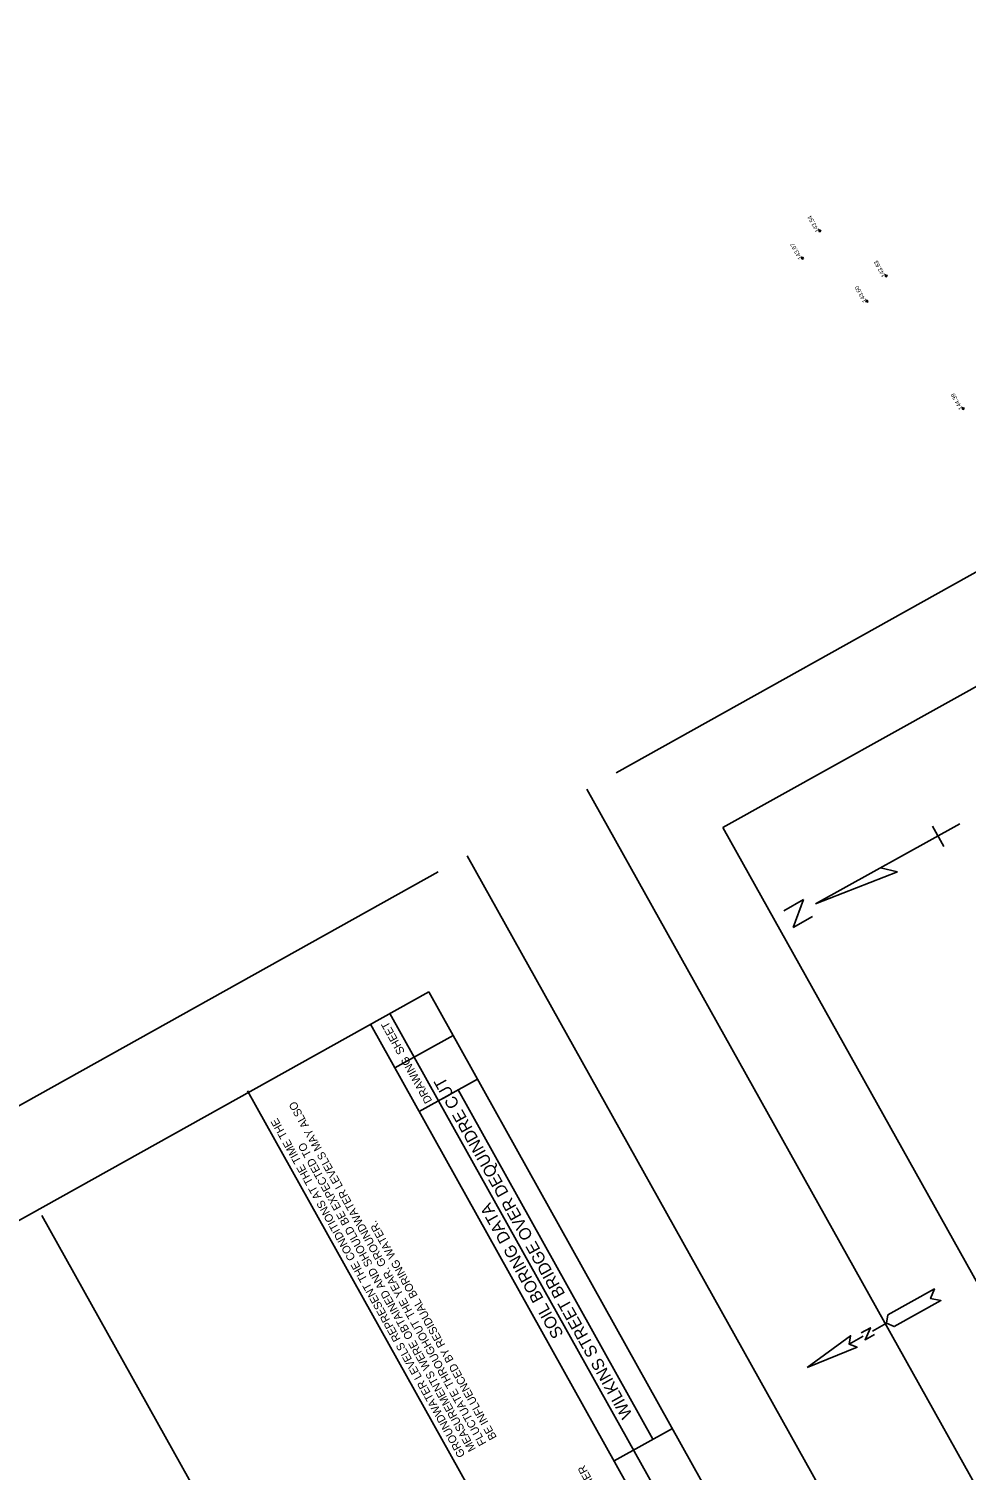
# Model space of a CAD drawing. Extents: x 13482447 to 13495412, y 324533 to 340229.
# Drawn here: x 13492579 to 13493141, y 331592 to 332457 of the extents above; entities that cross this region are included whole.
import ezdxf

# ---------------------------------------------------------------- set-up
doc = ezdxf.new("R2010")
doc.units = 0
for name, color, linetype in [('BORDER', 7, 'Continuous'), ('Default', 7, 'Continuous'), ('Level 1', 7, 'Continuous'), ('Level 63', 7, 'Continuous'), ('V-PVMT-IDEN', 7, 'Continuous'), ('V-TOPO-DRAN-SPOT', 7, 'Continuous')]:
    doc.layers.add(name, color=color, linetype=linetype)

# ---------------------------------------------------------------- blocks, each defined once
blk = doc.blocks.new('VERTN')
at = {"layer": 'Level 63'}
for p, q in [((0, 0.0104), (0, 0.0417)), ((0, -0.0417), (0, -0.0104))]:
    blk.add_line(p, q, dxfattribs=at)
for points in [[(0, 0.1354), (-0.013, 0.0312), (0, 0.0417), (0.013, 0.0312), (0, 0.1354)], [(-0.0078, -0.0104), (-0.0078, 0.0104), (0.0077, -0.0104), (0.0077, 0.0104)], [(0, -0.0417), (-0.013, -0.0521), (-0.013, -0.1562), (0, -0.1406), (0.013, -0.1562), (0.013, -0.0521), (0, -0.0417)]]:
    blk.add_lwpolyline(points, dxfattribs=at)

msp = doc.modelspace()

# ---------------------------------------------------------------- linework, layer by layer
at = {"layer": 'BORDER'}
for p, q in [((13493136.93, 331980.13), (13493050.27, 331932.13)), ((13493120.48, 331978.82), (13493127.24, 331966.62)), ((13493099.42, 331951.43), (13493089.37, 331953.79)), ((13493050.27, 331932.13), (13493099.42, 331951.43)), ((13493043.03, 331934.66), (13493031.26, 331928.03)), ((13493036.88, 331917.89), (13493043.03, 331934.66)), ((13493048.6, 331924.61), (13493036.88, 331917.89))]:
    msp.add_line(p, q, dxfattribs=at)
at = {"layer": 'Default'}
msp.add_lwpolyline([(13492586.34, 331745.09), (13492832.27, 331304.34)], dxfattribs=at)
at = {"layer": 'Level 1'}
for p, q in [((13493730.57, 332457.1), (13492930.67, 332010.77)), ((13493724.88, 332385.22), (13492994.84, 331977.87)), ((13493612.91, 330747.03), (13492913.2, 332001.03)), ((13493636.07, 330828.66), (13492994.84, 331977.87)), ((13493541.18, 330707.01), (13492841.48, 331961.01)), ((13492824.01, 331951.26), (13492024.11, 331504.93)), ((13492818.32, 331879.38), (13492088.28, 331472.03)), ((13493459.55, 330730.17), (13492818.32, 331879.38)), ((13493424.62, 330710.68), (13492783.39, 331859.89)), ((13492824.27, 331813.99), (13492795.03, 331866.38)), ((13492832.94, 331853.18), (13492798.01, 331833.69)), ((13492847.56, 331826.98), (13492812.62, 331807.49)), ((13493352.3, 330668.3), (13492709.75, 331819.87)), ((13492952.85, 331610.9), (13492835.91, 331820.49)), ((13493136.11, 331255.1), (13492824.27, 331813.99)), ((13492929.58, 331597.92), (13492964.52, 331617.41))]:
    msp.add_line(p, q, dxfattribs=at)
at = {"layer": 'V-TOPO-DRAN-SPOT'}
for p, q in [((13493052.07, 332335.47), (13493053.69, 332336.37)), ((13493053.35, 332335.08), (13493052.41, 332336.76)), ((13493041.66, 332319.07), (13493043.28, 332319.97)), ((13493042.93, 332318.68), (13493042, 332320.36)), ((13493091.84, 332308.5), (13493093.46, 332309.41)), ((13493093.11, 332308.12), (13493092.18, 332309.79)), ((13493080.33, 332293.3), (13493081.95, 332294.2)), ((13493081.61, 332292.91), (13493080.67, 332294.59)), ((13493138, 332228.89), (13493139.62, 332229.79)), ((13493139.28, 332228.5), (13493138.34, 332230.18))]:
    msp.add_line(p, q, dxfattribs=at)

# ---------------------------------------------------------------- block references
at = {"layer": 'V-PVMT-IDEN', "xscale": 307.2, "yscale": 307.2000000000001, "rotation": 119.16052892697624}
msp.add_blockref('VERTN', (13493081.66, 331674.23), dxfattribs=at)

# ---------------------------------------------------------------- texts
at = {"layer": 'BORDER'}
for s, p in [('FLUCTUATE THROUGHOUT THE YEAR. GROUNDWATER LEVELS MAY ALSO ', (13492853.03, 331608.61)), ('GROUNDWATER LEVELS REPRESENT THE CONDITIONS AT THE TIME THE ', (13492840.45, 331601.59)), ('MEASUREMENTS WERE OBTAINED AND SHOULD BE EXPECTED TO ', (13492846.74, 331605.1)), ('BE INFLUENCED BY RESIDUAL BORING WATER. ', (13492859.32, 331612.12)), ('THE SUBSURFACE CONDITIONS ARE THE SAME AT LOCATIONS OTHER ', (13493020.39, 331400.86))]:
    msp.add_text(s, height=4.8, rotation=119.16053, dxfattribs=at).set_placement(p)
at = {"layer": 'Level 1'}
for s, height, p in [('SHEET', 4.8, (13492804.2, 331843.38)), ('DRAWING', 4.8, (13492820.55, 331814)), ('WILKINS STREET BRIDGE OVER DEQUINDRE CUT', 7.2, (13492940.77, 331625.71)), ('SOIL BORING DATA', 7.2, (13492899.44, 331673.91))]:
    msp.add_text(s, height=height, rotation=119.16053, dxfattribs=at).set_placement(p)
at = {"layer": 'V-TOPO-DRAN-SPOT'}
for s, p in [('143.54', (13493052.88, 332335.92)), ('143.67', (13493042.47, 332319.52)), ('143.63', (13493092.65, 332308.96)), ('143.60', (13493081.14, 332293.75)), ('144.39', (13493138.81, 332229.34))]:
    msp.add_text(s, height=2.56, rotation=119.16053, dxfattribs=at).set_placement(p)

doc.saveas('drawing.dxf')
